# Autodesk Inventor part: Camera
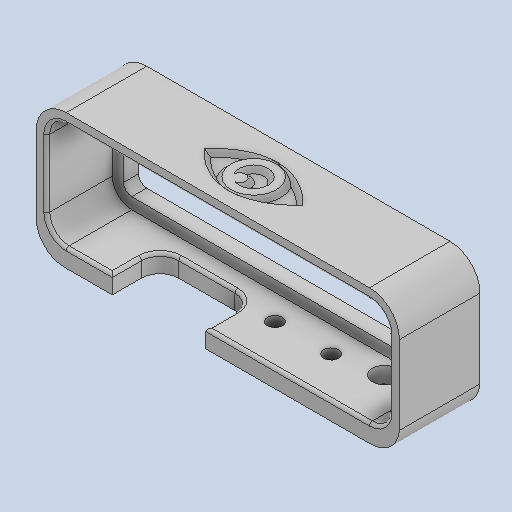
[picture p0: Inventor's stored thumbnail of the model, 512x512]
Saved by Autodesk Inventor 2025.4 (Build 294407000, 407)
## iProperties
Created: 2026-06
Part Number: Camera
Material: Generic
Document SubType Name: Modeling
Designer: AdminForWorker
Density: 1 g/cm^3
Appearance: Default
Title: Camera v15
Author: AdminForWorker
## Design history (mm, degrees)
feature "Support_cam"
body "Solid1"
